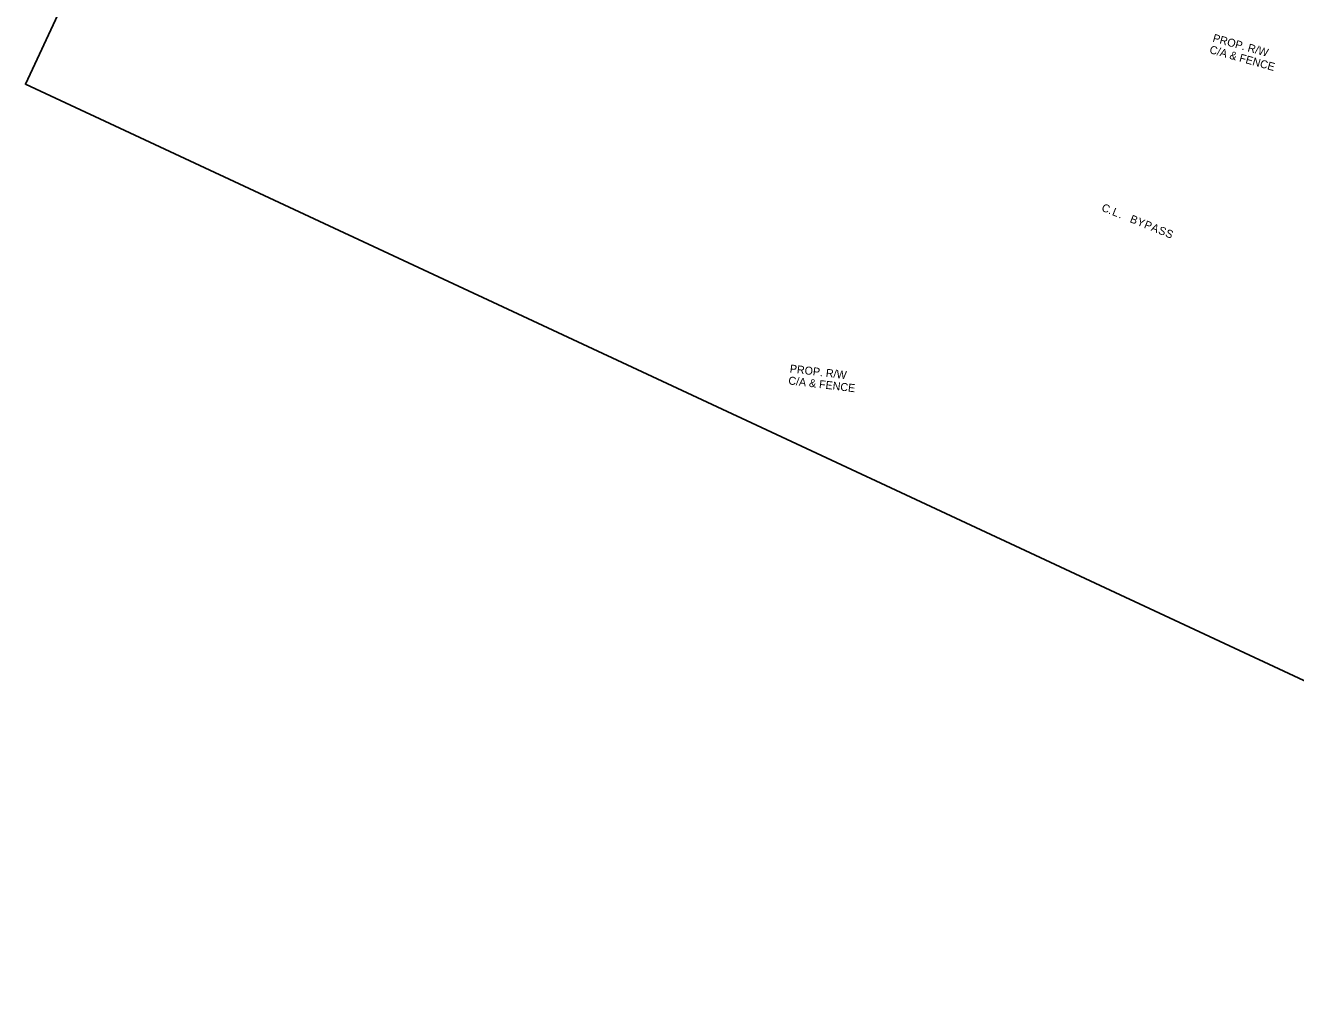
# Model space of a CAD drawing. Extents: x 980231 to 982096, y 1837566 to 1839185.
# Drawn here: x 980231 to 981183, y 1837566 to 1838284 of the extents above; entities that cross this region are included whole.
import ezdxf

# ---------------------------------------------------------------- set-up
doc = ezdxf.new("R2010")
doc.units = 0
doc.layers.add('G-Border-Sheet', color=7, linetype='Continuous')
doc.layers.add('R_Draft', color=7, linetype='Continuous')

msp = doc.modelspace()

# ---------------------------------------------------------------- linework, layer by layer
at = {"layer": 'G-Border-Sheet'}
msp.add_lwpolyline([(981897.02, 1838038.3), (981676.77, 1837565.97), (981495.51, 1837650.49), (980230.88, 1838240.2), (980451.13, 1838712.53), (980632.39, 1838628), (980601.86, 1838562.52), (980987.04, 1838382.91), (981017.57, 1838448.39), (981261.89, 1838334.46), (981227.36, 1838260.41), (981537.92, 1838115.59), (981572.45, 1838189.65)], close=True, dxfattribs=at)
msp.add_lwpolyline([(981897.02, 1838038.3), (981676.77, 1837565.97), (981495.51, 1837650.49), (980230.88, 1838240.2), (980451.13, 1838712.53), (980632.39, 1838628), (980601.86, 1838562.52), (980987.04, 1838382.91), (981017.57, 1838448.39), (981261.89, 1838334.46), (981227.36, 1838260.41), (981537.92, 1838115.59), (981572.45, 1838189.65)], close=True, dxfattribs=at)
msp.add_lwpolyline([(981897.02, 1838038.3), (981676.77, 1837565.97), (981495.51, 1837650.49), (980230.88, 1838240.2), (980451.13, 1838712.53), (980632.39, 1838628), (980601.86, 1838562.52), (980987.04, 1838382.91), (981017.57, 1838448.39), (981261.89, 1838334.46), (981227.36, 1838260.41), (981537.92, 1838115.59), (981572.45, 1838189.65)], close=True, dxfattribs=at)
msp.add_lwpolyline([(981897.02, 1838038.3), (981676.77, 1837565.97), (981495.51, 1837650.49), (980230.88, 1838240.2), (980451.13, 1838712.53), (980632.39, 1838628), (980601.86, 1838562.52), (980987.04, 1838382.91), (981017.57, 1838448.39), (981261.89, 1838334.46), (981227.36, 1838260.41), (981537.92, 1838115.59), (981572.45, 1838189.65)], close=True, dxfattribs=at)

# ---------------------------------------------------------------- texts
at = {"layer": 'R_Draft'}
for s, rotation, p in [('PROP. R/W', 344.42196, (981120.84, 1838272.33)), ('C/A & FENCE', 344.42196, (981118.42, 1838263.66)), ('C', 338.16792, (981037.4, 1838145.51)), ('.', 338.16792, (981042.67, 1838143.4)), ('L', 338.16792, (981045.39, 1838142.31)), ('.', 338.16792, (981050.39, 1838140.31)), ('B', 338.16792, (981058.67, 1838136.99)), ('Y', 338.16792, (981063.94, 1838134.88)), ('P', 338.16792, (981069.29, 1838132.74)), ('A', 338.16792, (981074.55, 1838130.63)), ('S', 338.16792, (981079.99, 1838128.45)), ('S', 338.16792, (981085.25, 1838126.34)), ('PROP. R/W', 353.18192, (980803.87, 1838024.22)), ('C/A & FENCE', 353.18192, (980802.8, 1838015.28))]:
    msp.add_text(s, height=6, rotation=rotation, dxfattribs=at).set_placement(p)

doc.saveas('drawing.dxf')
